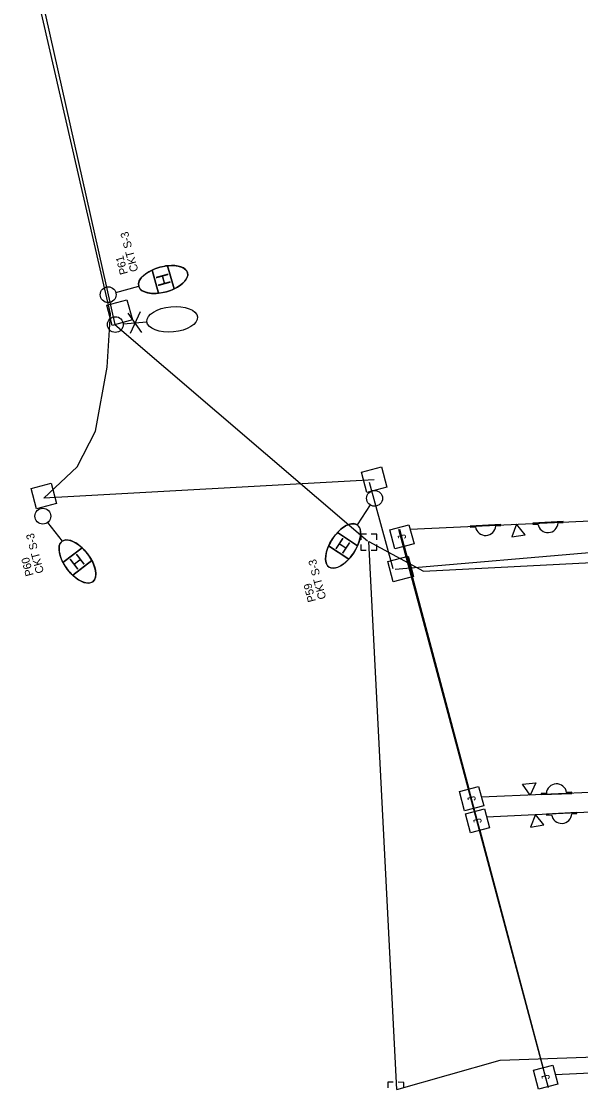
# Model space of a CAD drawing. Extents: x 925407 to 931638, y 609358 to 637063.
# Drawn here: x 930369.6 to 930544.2, y 629284.3 to 629618 of the extents above; entities that cross this region are included whole.
import ezdxf

# ---------------------------------------------------------------- set-up
doc = ezdxf.new("R2010")
doc.units = 0
for name, color, linetype in [('ActivePointCell_dp', 7, 'Continuous'), ('Bridge', 7, 'Continuous'), ('Conduit', 7, 'Continuous'), ('ConduitDB', 7, 'Continuous'), ('ConduitJB', 7, 'Continuous'), ('ConduitOT', 7, 'Continuous'), ('JunctBoxA', 7, 'Continuous'), ('LightingMisc', 7, 'Continuous'), ('LiteCond_ep', 7, 'Continuous'), ('Miscellaneous2', 7, 'Continuous'), ('PoleLight', 7, 'Continuous'), ('PoleLight_ep', 7, 'Continuous'), ('PullBox', 7, 'Continuous'), ('TextLabel', 7, 'Continuous')]:
    doc.layers.add(name, color=color, linetype=linetype)

msp = doc.modelspace()

# ---------------------------------------------------------------- linework, layer by layer
at = {"layer": 'Bridge'}
for q in [(930487.42, 629459.24), (930487.8, 629459.24), (930487.8, 629459.24)]:
    msp.add_line((930534.18, 629284.83), q, dxfattribs=at)
at = {"layer": 'Conduit'}
for p, q in [((930486.8, 629284.31), (930478.04, 629455.48)), ((930478.04, 629455.48), (930495.19, 629446.22)), ((930495.19, 629446.22), (930702, 629456.89)), ((930519.05, 629293.47), (930755.53, 629302.01)), ((930486.8, 629284.31), (930519.05, 629293.47))]:
    msp.add_line(p, q, dxfattribs=at)
at = {"layer": 'ConduitDB'}
for p, q in [((930479.73, 629474.82), (930376.6, 629469.07)), ((930486.25, 629446.88), (930698.37, 629465.04))]:
    msp.add_line(p, q, dxfattribs=at)
at = {"layer": 'ConduitJB'}
for p, q in [((930490.97, 629459.39), (930689.95, 629468.59)), ((930509.36, 629378.19), (930489.2, 629453.99)), ((930509.36, 629378.19), (930489.2, 629453.99)), ((930713.18, 629384.45), (930513.24, 629375.62)), ((930514.85, 629369.56), (930714.83, 629378.73)), ((930532.49, 629291.21), (930512.79, 629365.27)), ((930536.26, 629289.06), (930725.41, 629297.99))]:
    msp.add_line(p, q, dxfattribs=at)
at = {"layer": 'ConduitOT'}
for p, q in [((930397.38, 629526.67), (930370.31, 629644.91)), ((930396.33, 629509.99), (930397.38, 629526.67)), ((930392.69, 629489.99), (930396.33, 629509.99)), ((930387, 629478.8), (930392.69, 629489.99)), ((930376.6, 629469.07), (930387, 629478.8)), ((930485.68, 629446.94), (930478.3, 629473.9))]:
    msp.add_line(p, q, dxfattribs=at)
at = {"layer": 'LightingMisc'}
for p, q in [((930538.75, 629461.73), (930529.25, 629461.21)), ((930537.17, 629461.33), (930538.77, 629461.42)), ((930538.77, 629461.42), (930538.75, 629461.73)), ((930519.26, 629460.83), (930509.76, 629460.31)), ((930509.76, 629460.31), (930509.77, 629459.99)), ((930509.77, 629459.99), (930511.37, 629460.08)), ((930517.68, 629460.43), (930519.28, 629460.52)), ((930519.28, 629460.52), (930519.26, 629460.83)), ((930529.25, 629461.21), (930529.27, 629460.89)), ((930529.27, 629460.89), (930530.87, 629460.98)), ((930533.5, 629376.84), (930531.9, 629376.78)), ((930531.9, 629376.78), (930531.91, 629376.46)), ((930531.91, 629376.46), (930541.42, 629376.85)), ((930541.41, 629377.17), (930539.81, 629377.1)), ((930541.42, 629376.85), (930541.41, 629377.17)), ((930543.02, 629370.9), (930533.52, 629370.37)), ((930533.52, 629370.37), (930533.53, 629370.06)), ((930533.53, 629370.06), (930535.13, 629370.14)), ((930541.44, 629370.49), (930543.04, 629370.58)), ((930543.04, 629370.58), (930543.02, 629370.9))]:
    msp.add_line(p, q, dxfattribs=at)
for points in [[(930522.71, 629457), (930526.88, 629457.65), (930524.23, 629460.93)], [(930526.05, 629379.74), (930530.25, 629380.12), (930528.49, 629376.29)], [(930528.57, 629366.33), (930532.74, 629366.98), (930530.09, 629370.26)]]:
    msp.add_lwpolyline(points, close=True, dxfattribs=at)
for centre, start, end in [((930514.51, 629460.57), 188.912, 357.4336), ((930534, 629461.47), 188.912, 357.4336), ((930536.67, 629376.66), 8.0885, 176.6101), ((930538.27, 629370.64), 188.912, 357.4336)]:
    msp.add_arc(centre, 3.17, start, end, dxfattribs=at)
at = {"layer": 'LiteCond_ep'}
for p, q in [((930370.05, 629651.65), (930398.78, 629523.26)), ((930398.78, 629523.26), (930477.67, 629455.72))]:
    msp.add_line(p, q, dxfattribs=at)
at = {"layer": 'Miscellaneous2'}
for p, q in [((930417.25, 629534.41), (930415.25, 629541.65)), ((930410.43, 629540.31), (930412.44, 629533.07)), ((930412.44, 629533.07), (930412.44, 629533.07)), ((930417.25, 629534.41), (930417.25, 629534.41)), ((930474.54, 629454.15), (930468.27, 629458.3)), ((930468.27, 629458.3), (930468.27, 629458.3)), ((930388.54, 629453.54), (930382.57, 629448.98)), ((930465.51, 629454.13), (930465.51, 629454.13)), ((930465.51, 629454.13), (930471.78, 629449.98)), ((930382.57, 629448.98), (930382.57, 629448.98)), ((930385.6, 629445.01), (930391.57, 629449.56)), ((930385.6, 629445.01), (930385.6, 629445.01))]:
    msp.add_line(p, q, dxfattribs=at)
for centre, major_axis, start_param, end_param in [((930413.84, 629537.36), (-7.63, -2.12), 4.391271, 5.033538), ((930413.84, 629537.36), (-7.63, -2.12), 4.391241, 4.391271), ((930413.84, 629537.36), (-7.63, -2.12), 1.249648, 1.891946), ((930470.03, 629454.14), (4.37, 6.61), 1.249648, 1.891946), ((930387.07, 629449.27), (-4.8, 6.3), 4.391271, 5.033538), ((930470.03, 629454.14), (4.37, 6.61), 4.391271, 5.033538), ((930387.07, 629449.27), (-4.8, 6.3), 1.249648, 1.891946), ((930387.07, 629449.27), (-4.8, 6.3), 4.391241, 4.391271), ((930470.03, 629454.14), (4.37, 6.61), 4.391241, 4.391271)]:
    msp.add_ellipse(centre, major_axis=major_axis, ratio=0.5, start_param=start_param, end_param=end_param, dxfattribs=at)
at = {"layer": 'PoleLight'}
for p, q in [((930415.25, 629541.65), (930417.25, 629534.41)), ((930412.44, 629533.07), (930410.43, 629540.31)), ((930399.05, 629533.26), (930406.21, 629535.24)), ((930478.49, 629466.94), (930474.4, 629460.75)), ((930377.77, 629461.48), (930382.27, 629455.57)), ((930468.27, 629458.3), (930474.54, 629454.15)), ((930382.57, 629448.98), (930388.54, 629453.54)), ((930471.78, 629449.98), (930465.51, 629454.13)), ((930391.57, 629449.56), (930385.6, 629445.01))]:
    msp.add_line(p, q, dxfattribs=at)
for centre in [(930396.67, 629532.6), (930396.67, 629532.6), (930479.86, 629469), (930479.86, 629469), (930376.27, 629463.44), (930376.27, 629463.44)]:
    msp.add_circle(centre, 2.48, dxfattribs=at)
for centre, major_axis in [((930413.84, 629537.36), (-7.63, -2.12)), ((930470.03, 629454.14), (4.37, 6.61)), ((930387.07, 629449.27), (-4.8, 6.3))]:
    msp.add_ellipse(centre, major_axis=major_axis, ratio=0.5, dxfattribs=at)
for centre, major_axis, start_param, end_param in [((930413.84, 629537.36), (-7.63, -2.12), 1.891945, 4.391241), ((930413.84, 629537.36), (-7.63, -2.12), 5.033538, 6.283185), ((930413.84, 629537.36), (-7.63, -2.12), 0, 0.847605), ((930413.84, 629537.36), (-7.63, -2.12), 0.847605, 1.249648), ((930470.03, 629454.14), (4.37, 6.61), 0.847605, 1.249648), ((930470.03, 629454.14), (4.37, 6.61), 0, 0.847605), ((930470.03, 629454.14), (4.37, 6.61), 5.033538, 6.283185), ((930387.07, 629449.27), (-4.8, 6.3), 0, 0.847605), ((930387.07, 629449.27), (-4.8, 6.3), 5.033538, 6.283185), ((930387.07, 629449.27), (-4.8, 6.3), 0.847605, 1.249648), ((930470.03, 629454.14), (4.37, 6.61), 1.891945, 4.391241), ((930387.07, 629449.27), (-4.8, 6.3), 1.891945, 4.391241)]:
    msp.add_ellipse(centre, major_axis=major_axis, ratio=0.5, start_param=start_param, end_param=end_param, dxfattribs=at)
at = {"layer": 'PoleLight_ep'}
for p, q in [((930407.22, 629520.81), (930402.94, 629526.87)), ((930406.63, 629527.21), (930403.53, 629520.47)), ((930401.38, 629523.5), (930408.78, 629524.18))]:
    msp.add_line(p, q, dxfattribs=at)
msp.add_circle((930398.92, 629523.27), 2.47, dxfattribs=at)
msp.add_ellipse((930416.66, 629524.91), major_axis=(7.89, 0.73), ratio=0.5, dxfattribs=at)
at = {"layer": 'PullBox'}
for p, q in [((930396.22, 629529.35), (930402.55, 629531.04)), ((930397.9, 629523.02), (930396.22, 629529.35)), ((930402.55, 629531.04), (930404.23, 629524.71)), ((930404.23, 629524.71), (930397.9, 629523.02)), ((930475.73, 629477.14), (930482.06, 629478.83)), ((930482.06, 629478.83), (930483.74, 629472.5)), ((930477.41, 629470.81), (930475.73, 629477.14)), ((930372.58, 629472.06), (930378.91, 629473.74)), ((930374.26, 629465.73), (930372.58, 629472.06)), ((930378.91, 629473.74), (930380.59, 629467.41)), ((930483.74, 629472.5), (930477.41, 629470.81)), ((930380.59, 629467.41), (930374.26, 629465.73)), ((930484.62, 629459.18), (930490.6, 629460.77)), ((930486.21, 629453.19), (930484.62, 629459.18)), ((930490.6, 629460.77), (930492.19, 629454.78)), ((930492.19, 629454.78), (930486.21, 629453.19)), ((930484.03, 629449.24), (930490.36, 629450.92)), ((930485.71, 629442.91), (930484.03, 629449.24)), ((930490.36, 629450.92), (930492.04, 629444.59)), ((930492.04, 629444.59), (930485.71, 629442.91)), ((930506.36, 629377.39), (930512.35, 629378.98)), ((930512.35, 629378.98), (930513.94, 629373)), ((930507.96, 629371.41), (930506.36, 629377.39)), ((930513.94, 629373), (930507.96, 629371.41)), ((930508.21, 629370.46), (930514.19, 629372.06)), ((930514.19, 629372.06), (930515.78, 629366.07)), ((930509.8, 629364.48), (930508.21, 629370.46)), ((930515.78, 629366.07), (930509.8, 629364.48)), ((930529.49, 629290.41), (930535.48, 629292)), ((930535.48, 629292), (930537.07, 629286.02)), ((930531.08, 629284.42), (930529.49, 629290.41)), ((930537.07, 629286.02), (930531.08, 629284.42))]:
    msp.add_line(p, q, dxfattribs=at)
for points in [[(930477.3, 629457.82), (930475.62, 629457.84), (930475.61, 629456.08)], [(930480.61, 629456.03), (930480.62, 629457.79), (930478.85, 629457.81)], [(930475.59, 629454.58), (930475.58, 629452.84), (930477.25, 629452.83)], [(930478.8, 629452.81), (930480.58, 629452.8)], [(930480.58, 629452.8), (930480.59, 629454.53)], [(930485.7, 629286.62), (930484.03, 629286.63), (930484.01, 629284.87)], [(930489.01, 629284.82), (930489.03, 629286.58), (930487.26, 629286.6)]]:
    msp.add_lwpolyline(points, dxfattribs=at)

# ---------------------------------------------------------------- texts
at = {"layer": 'ActivePointCell_dp'}
for s, p in [('CKT S-3', (930406.11, 629540.1)), ('P61', (930402.87, 629539.24)), ('CKT S-3', (930376.65, 629445.9)), ('P60', (930373.41, 629445.04)), ('CKT S-3', (930464.8, 629437.8)), ('P59', (930461.56, 629436.94))]:
    msp.add_text(s, height=2.5, rotation=104.7826, dxfattribs=at).set_placement(p)
at = {"layer": 'JunctBoxA'}
for p in [(930489.82, 629456.49), (930511.57, 629374.7), (930513.41, 629367.77), (930534.69, 629287.72)]:
    msp.add_text('J', height=2.48, rotation=104.8905, dxfattribs=at).set_placement(p)
at = {"layer": 'TextLabel'}
for rotation, p in [(285.5029, (930411.42, 629538.59)), (146.5091, (930472.65, 629454.8)), (217.3207, (930387.31, 629451.97))]:
    msp.add_text('H', height=4, rotation=rotation, dxfattribs=at).set_placement(p)

doc.saveas('drawing.dxf')
